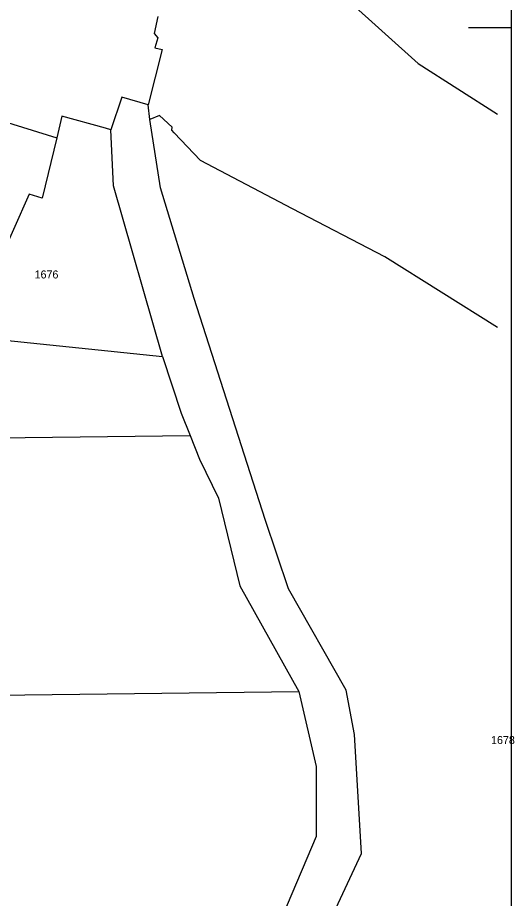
# Model space of a CAD drawing. Extents: x -583721 to -583071, y -1166145 to -1165065.
# Drawn here: x -583164 to -583070.9, y -1165749.9 to -1165584.9 of the extents above; entities that cross this region are included whole.
import ezdxf

# ---------------------------------------------------------------- set-up
doc = ezdxf.new("R2010")
doc.units = 0
for name, color, linetype in [('01_DOPRAVA', 7, 'Continuous'), ('56', 7, 'Continuous'), ('Parcelní čísla', 7, 'Continuous')]:
    doc.layers.add(name, color=color, linetype=linetype)

msp = doc.modelspace()

# ---------------------------------------------------------------- linework, layer by layer
at = {"layer": '01_DOPRAVA'}
for p, q in [((-583139.23, -1165603.98), (-583139.56, -1165601.27)), ((-583216.29, -1165664.24), (-583131.67, -1165663.22)), ((-583214.03, -1165712.42), (-583111.31, -1165711.19))]:
    msp.add_line(p, q, dxfattribs=at)
for points in [[(-583114.94, -1165570.1), (-583088.92, -1165593.54), (-583074.07, -1165603)], [(-583137.75, -1165584.74), (-583138.42, -1165587.89), (-583137.75, -1165588.71), (-583138.26, -1165590.59), (-583136.89, -1165590.9), (-583139.56, -1165601.27)], [(-583139.56, -1165601.27), (-583144.49, -1165599.85), (-583146.52, -1165605.94)], [(-583189.56, -1165601.59), (-583179.27, -1165605.61), (-583177.81, -1165600.88), (-583156.66, -1165607.42)], [(-583146.52, -1165605.94), (-583147.56, -1165605.65), (-583155.7, -1165603.4), (-583156.66, -1165607.42)], [(-583074.07, -1165642.97), (-583095.2, -1165629.75), (-583112.47, -1165620.73), (-583129.73, -1165611.71), (-583134.65, -1165606.49), (-583135.09, -1165606.03), (-583135.03, -1165605.47), (-583137.42, -1165603.24), (-583139.23, -1165603.98)], [(-583117.12, -1165791.46), (-583116.29, -1165779.51), (-583110.48, -1165764.97), (-583099.53, -1165741.52), (-583100.86, -1165719.24), (-583102.45, -1165710.91), (-583113.24, -1165691.92), (-583117.6, -1165678.92), (-583130.91, -1165637.56), (-583137.23, -1165616.79), (-583139.23, -1165603.98)], [(-583136.85, -1165648.41), (-583146.03, -1165616.46), (-583146.52, -1165605.94)], [(-583156.66, -1165607.42), (-583159.38, -1165618.75), (-583161.81, -1165618), (-583167.75, -1165631.23), (-583180.41, -1165628.61), (-583186.27, -1165637.89), (-583208.68, -1165647.1), (-583216.1, -1165647.85)], [(-583216.32, -1165649.81), (-583207.78, -1165650.22), (-583201.32, -1165648.6), (-583189.4, -1165642.98), (-583136.85, -1165648.41)], [(-583136.85, -1165648.41), (-583133.34, -1165659.02), (-583131.67, -1165663.22)], [(-583131.67, -1165663.22), (-583129.91, -1165667.64), (-583126.33, -1165674.98), (-583122.36, -1165691.37), (-583111.31, -1165711.19)], [(-583111.31, -1165711.19), (-583108.06, -1165725.24), (-583108.03, -1165738.33), (-583122.6, -1165772.66), (-583125.01, -1165781.15), (-583127.6, -1165810.04), (-583129.98, -1165835.69), (-583134.92, -1165854.65), (-583138.16, -1165860.06), (-583151.44, -1165876.82), (-583162.97, -1165902.22)]]:
    msp.add_lwpolyline(points, dxfattribs=at)
at = {"layer": '56'}
msp.add_line((-583071.47, -1165586.82), (-583079.47, -1165586.82), dxfattribs=at)
msp.add_lwpolyline([(-583516.97, -1166111.82), (-583516.97, -1165166.82), (-583071.47, -1165166.82), (-583071.47, -1166111.82)], close=True, dxfattribs=at)

# ---------------------------------------------------------------- texts
at = {"layer": 'Parcelní čísla'}
for s, p in [('1676', (-583160.82, -1165633.79)), ('1678', (-583075.27, -1165721.02))]:
    msp.add_text(s, height=1.5, dxfattribs=at).set_placement(p)

doc.saveas('drawing.dxf')
